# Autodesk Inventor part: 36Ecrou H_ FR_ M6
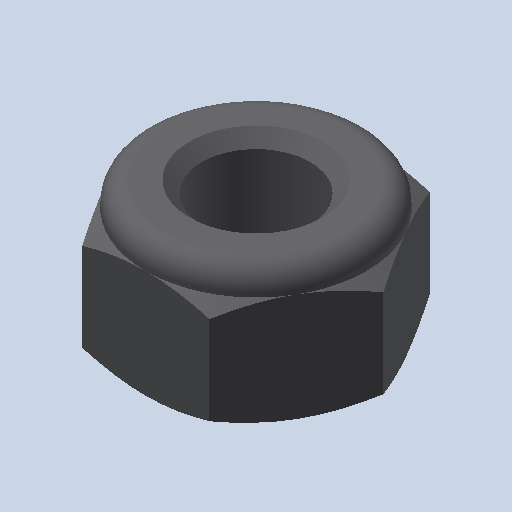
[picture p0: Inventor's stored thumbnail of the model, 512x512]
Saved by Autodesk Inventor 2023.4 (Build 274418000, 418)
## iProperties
Created: 2011-01
Part Number: 36Ecrou H_ FR_ M6
Document SubType Name: Modeling
Designer: eric
Density: 1 g/cm^3
Mass: 0.384243 g
Surface Area: 4.02228 cm^2
Volume: 0.384243 cm^3
Material: Générique
Appearance: Red
Author: eric
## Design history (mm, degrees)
feature "Base1"
node "Corps solides"
node "Corps surfaciques"
node "Solide1"
